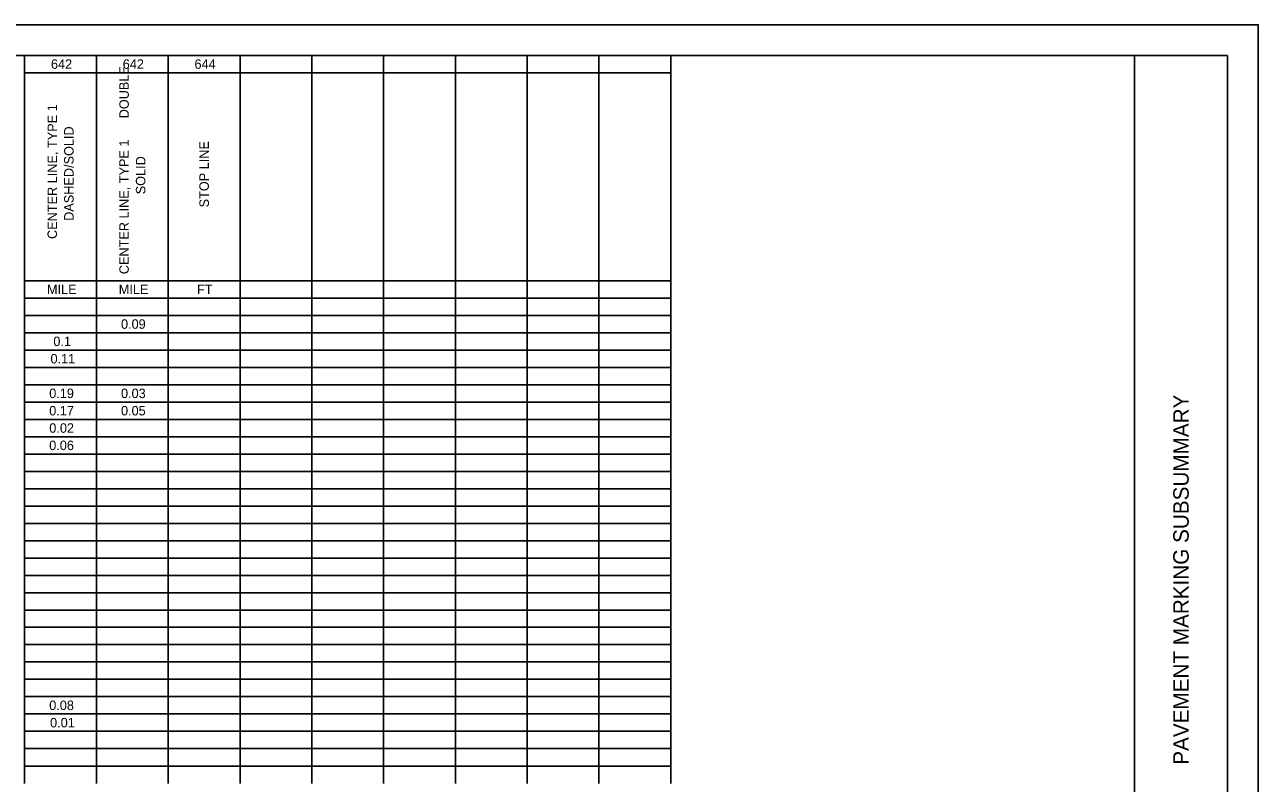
# Model space of a CAD drawing. Extents: x 0 to 34, y 0 to 22.
# Drawn here: x 14.06 to 34, y 9.74 to 22 of the extents above; entities that cross this region are included whole.
import ezdxf

# ---------------------------------------------------------------- set-up
doc = ezdxf.new("R2010")
doc.units = 0
for name, color, linetype in [('SH_Border', 7, 'Continuous'), ('SH_Cut_Line', 7, 'Continuous'), ('SH_Data', 7, 'Continuous'), ('SH_Text', 7, 'Continuous')]:
    doc.layers.add(name, color=color, linetype=linetype)

msp = doc.modelspace()

# ---------------------------------------------------------------- linework, layer by layer
at = {"layer": 'SH_Border'}
msp.add_line((32, 0.5), (32, 21.5), dxfattribs=at)
msp.add_lwpolyline([(1.5, 21.5), (33.5, 21.5), (33.5, 0.5), (1.5, 0.5)], close=True, dxfattribs=at)
at = {"layer": 'SH_Cut_Line'}
msp.add_lwpolyline([(0, 0), (34, 0), (34, 22), (0, 22)], close=True, dxfattribs=at)
at = {"layer": 'SH_Text'}
for p, q in [((14.062, 21.504), (16.383, 21.504)), ((14.062, 21.504), (14.062, 21.223)), ((15.222, 21.504), (15.222, 21.223)), ((16.383, 21.504), (21.024, 21.504)), ((16.383, 21.504), (16.383, 21.223)), ((17.543, 21.504), (17.543, 21.223)), ((18.703, 21.504), (18.703, 21.223)), ((19.863, 21.504), (19.863, 21.223)), ((21.024, 21.504), (23.344, 21.504)), ((21.024, 21.504), (21.024, 21.223)), ((22.184, 21.504), (22.184, 21.223)), ((23.344, 21.504), (24.504, 21.504)), ((23.344, 21.504), (23.344, 21.223)), ((24.504, 21.504), (24.504, 21.223)), ((14.062, 21.223), (16.383, 21.223)), ((14.062, 21.223), (14.062, 20.943)), ((15.222, 21.223), (15.222, 20.943)), ((16.383, 21.223), (21.024, 21.223)), ((16.383, 21.223), (16.383, 20.943)), ((17.543, 21.223), (17.543, 20.943)), ((18.703, 21.223), (18.703, 20.943)), ((19.863, 21.223), (19.863, 20.943)), ((21.024, 21.223), (23.344, 21.223)), ((21.024, 21.223), (21.024, 20.943)), ((22.184, 21.223), (22.184, 20.943)), ((23.344, 21.223), (24.504, 21.223)), ((23.344, 21.223), (23.344, 20.943)), ((24.504, 21.223), (24.504, 20.943)), ((14.062, 20.943), (14.062, 20.663)), ((15.222, 20.943), (15.222, 20.663)), ((16.383, 20.943), (16.383, 20.663)), ((17.543, 20.943), (17.543, 20.663)), ((18.703, 20.943), (18.703, 20.663)), ((19.863, 20.943), (19.863, 20.663)), ((21.024, 20.943), (21.024, 20.663)), ((22.184, 20.943), (22.184, 20.663)), ((23.344, 20.943), (23.344, 20.663)), ((24.504, 20.943), (24.504, 20.663)), ((14.062, 20.663), (14.062, 20.383)), ((15.222, 20.663), (15.222, 20.383)), ((16.383, 20.663), (16.383, 20.383)), ((17.543, 20.663), (17.543, 20.383)), ((18.703, 20.663), (18.703, 20.383)), ((19.863, 20.663), (19.863, 20.383)), ((21.024, 20.663), (21.024, 20.383)), ((22.184, 20.663), (22.184, 20.383)), ((23.344, 20.663), (23.344, 20.383)), ((24.504, 20.663), (24.504, 20.383)), ((14.062, 20.383), (14.062, 20.103)), ((15.222, 20.383), (15.222, 20.103)), ((16.383, 20.383), (16.383, 20.103)), ((17.543, 20.383), (17.543, 20.103)), ((18.703, 20.383), (18.703, 20.103)), ((19.863, 20.383), (19.863, 20.103)), ((21.024, 20.383), (21.024, 20.103)), ((22.184, 20.383), (22.184, 20.103)), ((23.344, 20.383), (23.344, 20.103)), ((24.504, 20.383), (24.504, 20.103)), ((14.062, 20.103), (14.062, 19.823)), ((15.222, 20.103), (15.222, 19.823)), ((16.383, 20.103), (16.383, 19.823)), ((17.543, 20.103), (17.543, 19.823)), ((18.703, 20.103), (18.703, 19.823)), ((19.863, 20.103), (19.863, 19.823)), ((21.024, 20.103), (21.024, 19.823)), ((22.184, 20.103), (22.184, 19.823)), ((23.344, 20.103), (23.344, 19.823)), ((24.504, 20.103), (24.504, 19.823)), ((14.062, 19.823), (14.062, 19.543)), ((15.222, 19.823), (15.222, 19.543)), ((16.383, 19.823), (16.383, 19.543)), ((17.543, 19.823), (17.543, 19.543)), ((18.703, 19.823), (18.703, 19.543)), ((19.863, 19.823), (19.863, 19.543)), ((21.024, 19.823), (21.024, 19.543)), ((22.184, 19.823), (22.184, 19.543)), ((23.344, 19.823), (23.344, 19.543)), ((24.504, 19.823), (24.504, 19.543)), ((14.062, 19.543), (14.062, 18.983)), ((15.222, 19.543), (15.222, 18.983)), ((16.383, 19.543), (16.383, 18.983)), ((17.543, 19.543), (17.543, 18.983)), ((18.703, 19.543), (18.703, 18.983)), ((19.863, 19.543), (19.863, 18.983)), ((21.024, 19.543), (21.024, 18.983)), ((22.184, 19.543), (22.184, 18.983)), ((23.344, 19.543), (23.344, 18.983)), ((24.504, 19.543), (24.504, 18.983)), ((14.062, 18.983), (14.062, 18.143)), ((15.222, 18.983), (15.222, 18.143)), ((16.383, 18.983), (16.383, 18.143)), ((17.543, 18.983), (17.543, 18.143)), ((18.703, 18.983), (18.703, 18.143)), ((19.863, 18.983), (19.863, 18.143)), ((21.024, 18.983), (21.024, 18.143)), ((22.184, 18.983), (22.184, 18.143)), ((23.344, 18.983), (23.344, 18.143)), ((24.504, 18.983), (24.504, 18.143)), ((14.062, 18.143), (14.062, 17.863)), ((15.222, 18.143), (15.222, 17.863)), ((16.383, 18.143), (16.383, 17.863)), ((17.543, 18.143), (17.543, 17.863)), ((18.703, 18.143), (18.703, 17.863)), ((19.863, 18.143), (19.863, 17.863)), ((21.024, 18.143), (21.024, 17.863)), ((22.184, 18.143), (22.184, 17.863)), ((23.344, 18.143), (23.344, 17.863)), ((24.504, 18.143), (24.504, 17.863)), ((14.062, 17.863), (16.383, 17.863)), ((14.062, 17.863), (14.062, 17.303)), ((15.222, 17.863), (15.222, 17.303)), ((16.383, 17.863), (21.024, 17.863)), ((16.383, 17.863), (16.383, 17.303)), ((17.543, 17.863), (17.543, 17.303)), ((18.703, 17.863), (18.703, 17.303)), ((19.863, 17.863), (19.863, 17.303)), ((21.024, 17.863), (23.344, 17.863)), ((21.024, 17.863), (21.024, 17.303)), ((22.184, 17.863), (22.184, 17.303)), ((23.344, 17.863), (24.504, 17.863)), ((23.344, 17.863), (23.344, 17.303)), ((24.504, 17.863), (24.504, 17.303)), ((14.062, 17.583), (16.383, 17.583)), ((16.383, 17.583), (21.024, 17.583)), ((21.024, 17.583), (23.344, 17.583)), ((23.344, 17.583), (24.504, 17.583)), ((14.062, 17.303), (16.383, 17.303)), ((14.062, 17.303), (14.062, 17.023)), ((15.222, 17.303), (15.222, 17.023)), ((16.383, 17.303), (21.024, 17.303)), ((16.383, 17.303), (16.383, 17.023)), ((17.543, 17.303), (17.543, 17.023)), ((18.703, 17.303), (18.703, 17.023)), ((19.863, 17.303), (19.863, 17.023)), ((21.024, 17.303), (23.344, 17.303)), ((21.024, 17.303), (21.024, 17.023)), ((22.184, 17.303), (22.184, 17.023)), ((23.344, 17.303), (24.504, 17.303)), ((23.344, 17.303), (23.344, 17.023)), ((24.504, 17.303), (24.504, 17.023)), ((14.062, 17.023), (16.383, 17.023)), ((14.062, 17.023), (14.062, 15.903)), ((15.222, 17.023), (15.222, 15.903)), ((16.383, 17.023), (21.024, 17.023)), ((16.383, 17.023), (16.383, 15.903)), ((17.543, 17.023), (17.543, 15.903)), ((18.703, 17.023), (18.703, 15.903)), ((19.863, 17.023), (19.863, 15.903)), ((21.024, 17.023), (23.344, 17.023)), ((21.024, 17.023), (21.024, 15.903)), ((22.184, 17.023), (22.184, 15.903)), ((23.344, 17.023), (24.504, 17.023)), ((23.344, 17.023), (23.344, 15.903)), ((24.504, 17.023), (24.504, 15.903)), ((14.062, 16.743), (16.383, 16.743)), ((16.383, 16.743), (21.024, 16.743)), ((21.024, 16.743), (23.344, 16.743)), ((23.344, 16.743), (24.504, 16.743)), ((14.062, 16.463), (16.383, 16.463)), ((16.383, 16.463), (21.024, 16.463)), ((21.024, 16.463), (23.344, 16.463)), ((23.344, 16.463), (24.504, 16.463)), ((14.062, 16.183), (16.383, 16.183)), ((16.383, 16.183), (21.024, 16.183)), ((21.024, 16.183), (23.344, 16.183)), ((23.344, 16.183), (24.504, 16.183)), ((14.062, 15.903), (16.383, 15.903)), ((14.062, 15.903), (14.062, 15.622)), ((15.222, 15.903), (15.222, 15.622)), ((16.383, 15.903), (21.024, 15.903)), ((16.383, 15.903), (16.383, 15.622)), ((17.543, 15.903), (17.543, 15.622)), ((18.703, 15.903), (18.703, 15.622)), ((19.863, 15.903), (19.863, 15.622)), ((21.024, 15.903), (23.344, 15.903)), ((21.024, 15.903), (21.024, 15.622)), ((22.184, 15.903), (22.184, 15.622)), ((23.344, 15.903), (24.504, 15.903)), ((23.344, 15.903), (23.344, 15.622)), ((24.504, 15.903), (24.504, 15.622)), ((14.062, 15.622), (16.383, 15.622)), ((14.062, 15.622), (14.062, 15.062)), ((15.222, 15.622), (15.222, 15.062)), ((16.383, 15.622), (21.024, 15.622)), ((16.383, 15.622), (16.383, 15.062)), ((17.543, 15.622), (17.543, 15.062)), ((18.703, 15.622), (18.703, 15.062)), ((19.863, 15.622), (19.863, 15.062)), ((21.024, 15.622), (23.344, 15.622)), ((21.024, 15.622), (21.024, 15.062)), ((22.184, 15.622), (22.184, 15.062)), ((23.344, 15.622), (24.504, 15.622)), ((23.344, 15.622), (23.344, 15.062)), ((24.504, 15.622), (24.504, 15.062)), ((14.062, 15.342), (16.383, 15.342)), ((16.383, 15.342), (21.024, 15.342)), ((21.024, 15.342), (23.344, 15.342)), ((23.344, 15.342), (24.504, 15.342)), ((14.062, 15.062), (16.383, 15.062)), ((14.062, 15.062), (14.062, 14.502)), ((15.222, 15.062), (15.222, 14.502)), ((16.383, 15.062), (21.024, 15.062)), ((16.383, 15.062), (16.383, 14.502)), ((17.543, 15.062), (17.543, 14.502)), ((18.703, 15.062), (18.703, 14.502)), ((19.863, 15.062), (19.863, 14.502)), ((21.024, 15.062), (23.344, 15.062)), ((21.024, 15.062), (21.024, 14.502)), ((22.184, 15.062), (22.184, 14.502)), ((23.344, 15.062), (24.504, 15.062)), ((23.344, 15.062), (23.344, 14.502)), ((24.504, 15.062), (24.504, 14.502)), ((14.062, 14.782), (16.383, 14.782)), ((16.383, 14.782), (21.024, 14.782)), ((21.024, 14.782), (23.344, 14.782)), ((23.344, 14.782), (24.504, 14.782)), ((14.062, 14.502), (16.383, 14.502)), ((14.062, 14.502), (14.062, 14.222)), ((15.222, 14.502), (15.222, 14.222)), ((16.383, 14.502), (21.024, 14.502)), ((16.383, 14.502), (16.383, 14.222)), ((17.543, 14.502), (17.543, 14.222)), ((18.703, 14.502), (18.703, 14.222)), ((19.863, 14.502), (19.863, 14.222)), ((21.024, 14.502), (23.344, 14.502)), ((21.024, 14.502), (21.024, 14.222)), ((22.184, 14.502), (22.184, 14.222)), ((23.344, 14.502), (24.504, 14.502)), ((23.344, 14.502), (23.344, 14.222)), ((24.504, 14.502), (24.504, 14.222)), ((14.062, 14.222), (16.383, 14.222)), ((14.062, 14.222), (14.062, 13.662)), ((15.222, 14.222), (15.222, 13.662)), ((16.383, 14.222), (21.024, 14.222)), ((16.383, 14.222), (16.383, 13.662)), ((17.543, 14.222), (17.543, 13.662)), ((18.703, 14.222), (18.703, 13.662)), ((19.863, 14.222), (19.863, 13.662)), ((21.024, 14.222), (23.344, 14.222)), ((21.024, 14.222), (21.024, 13.662)), ((22.184, 14.222), (22.184, 13.662)), ((23.344, 14.222), (24.504, 14.222)), ((23.344, 14.222), (23.344, 13.662)), ((24.504, 14.222), (24.504, 13.662)), ((14.062, 13.942), (16.383, 13.942)), ((16.383, 13.942), (21.024, 13.942)), ((21.024, 13.942), (23.344, 13.942)), ((23.344, 13.942), (24.504, 13.942)), ((14.062, 13.662), (16.383, 13.662)), ((14.062, 13.662), (14.062, 13.382)), ((15.222, 13.662), (15.222, 13.382)), ((16.383, 13.662), (21.024, 13.662)), ((16.383, 13.662), (16.383, 13.382)), ((17.543, 13.662), (17.543, 13.382)), ((18.703, 13.662), (18.703, 13.382)), ((19.863, 13.662), (19.863, 13.382)), ((21.024, 13.662), (23.344, 13.662)), ((21.024, 13.662), (21.024, 13.382)), ((22.184, 13.662), (22.184, 13.382)), ((23.344, 13.662), (24.504, 13.662)), ((23.344, 13.662), (23.344, 13.382)), ((24.504, 13.662), (24.504, 13.382)), ((14.062, 13.382), (16.383, 13.382)), ((14.062, 13.382), (14.062, 12.542)), ((15.222, 13.382), (15.222, 12.542)), ((16.383, 13.382), (21.024, 13.382)), ((16.383, 13.382), (16.383, 12.542)), ((17.543, 13.382), (17.543, 12.542)), ((18.703, 13.382), (18.703, 12.542)), ((19.863, 13.382), (19.863, 12.542)), ((21.024, 13.382), (23.344, 13.382)), ((21.024, 13.382), (21.024, 12.542)), ((22.184, 13.382), (22.184, 12.542)), ((23.344, 13.382), (24.504, 13.382)), ((23.344, 13.382), (23.344, 12.542)), ((24.504, 13.382), (24.504, 12.542)), ((14.062, 13.102), (16.383, 13.102)), ((16.383, 13.102), (21.024, 13.102)), ((21.024, 13.102), (23.344, 13.102)), ((23.344, 13.102), (24.504, 13.102)), ((14.062, 12.822), (16.383, 12.822)), ((16.383, 12.822), (21.024, 12.822)), ((21.024, 12.822), (23.344, 12.822)), ((23.344, 12.822), (24.504, 12.822)), ((14.062, 12.542), (16.383, 12.542)), ((14.062, 12.542), (14.062, 11.982)), ((15.222, 12.542), (15.222, 11.982)), ((16.383, 12.542), (21.024, 12.542)), ((16.383, 12.542), (16.383, 11.982)), ((17.543, 12.542), (17.543, 11.982)), ((18.703, 12.542), (18.703, 11.982)), ((19.863, 12.542), (19.863, 11.982)), ((21.024, 12.542), (23.344, 12.542)), ((21.024, 12.542), (21.024, 11.982)), ((22.184, 12.542), (22.184, 11.982)), ((23.344, 12.542), (24.504, 12.542)), ((23.344, 12.542), (23.344, 11.982)), ((24.504, 12.542), (24.504, 11.982)), ((14.062, 12.262), (16.383, 12.262)), ((16.383, 12.262), (21.024, 12.262)), ((21.024, 12.262), (23.344, 12.262)), ((23.344, 12.262), (24.504, 12.262)), ((14.062, 11.982), (16.383, 11.982)), ((14.062, 11.982), (14.062, 11.142)), ((15.222, 11.982), (15.222, 11.142)), ((16.383, 11.982), (21.024, 11.982)), ((16.383, 11.982), (16.383, 11.142)), ((17.543, 11.982), (17.543, 11.142)), ((18.703, 11.982), (18.703, 11.142)), ((19.863, 11.982), (19.863, 11.142)), ((21.024, 11.982), (23.344, 11.982)), ((21.024, 11.982), (21.024, 11.142)), ((22.184, 11.982), (22.184, 11.142)), ((23.344, 11.982), (24.504, 11.982)), ((23.344, 11.982), (23.344, 11.142)), ((24.504, 11.982), (24.504, 11.142)), ((14.062, 11.702), (16.383, 11.702)), ((16.383, 11.702), (21.024, 11.702)), ((21.024, 11.702), (23.344, 11.702)), ((23.344, 11.702), (24.504, 11.702)), ((14.062, 11.422), (16.383, 11.422)), ((16.383, 11.422), (21.024, 11.422)), ((21.024, 11.422), (23.344, 11.422)), ((23.344, 11.422), (24.504, 11.422)), ((14.062, 11.142), (16.383, 11.142)), ((14.062, 11.142), (14.062, 10.582)), ((15.222, 11.142), (15.222, 10.582)), ((16.383, 11.142), (21.024, 11.142)), ((16.383, 11.142), (16.383, 10.582)), ((17.543, 11.142), (17.543, 10.582)), ((18.703, 11.142), (18.703, 10.582)), ((19.863, 11.142), (19.863, 10.582)), ((21.024, 11.142), (23.344, 11.142)), ((21.024, 11.142), (21.024, 10.582)), ((22.184, 11.142), (22.184, 10.582)), ((23.344, 11.142), (24.504, 11.142)), ((23.344, 11.142), (23.344, 10.582)), ((24.504, 11.142), (24.504, 10.582)), ((14.062, 10.862), (16.383, 10.862)), ((16.383, 10.862), (21.024, 10.862)), ((21.024, 10.862), (23.344, 10.862)), ((23.344, 10.862), (24.504, 10.862)), ((14.062, 10.582), (16.383, 10.582)), ((14.062, 10.582), (14.062, 9.741)), ((15.222, 10.582), (15.222, 9.741)), ((16.383, 10.582), (21.024, 10.582)), ((16.383, 10.582), (16.383, 9.741)), ((17.543, 10.582), (17.543, 9.741)), ((18.703, 10.582), (18.703, 9.741)), ((19.863, 10.582), (19.863, 9.741)), ((21.024, 10.582), (23.344, 10.582)), ((21.024, 10.582), (21.024, 9.741)), ((22.184, 10.582), (22.184, 9.741)), ((23.344, 10.582), (24.504, 10.582)), ((23.344, 10.582), (23.344, 9.741)), ((24.504, 10.582), (24.504, 9.741)), ((14.062, 10.302), (16.383, 10.302)), ((16.383, 10.302), (21.024, 10.302)), ((21.024, 10.302), (23.344, 10.302)), ((23.344, 10.302), (24.504, 10.302)), ((14.062, 10.021), (16.383, 10.021)), ((16.383, 10.021), (21.024, 10.021)), ((21.024, 10.021), (23.344, 10.021)), ((23.344, 10.021), (24.504, 10.021))]:
    msp.add_line(p, q, dxfattribs=at)

# ---------------------------------------------------------------- texts
at = {"layer": 'SH_Data'}
msp.add_text('PAVEMENT MARKING SUBSUMMARY', height=0.25, rotation=90, dxfattribs=at).set_placement((32.875, 10.041))
at = {"layer": 'SH_Text'}
for s, p in [('642', (14.487, 21.287)), ('642', (15.647, 21.287)), ('644', (16.807, 21.287)), ('MILE', (14.423, 17.646)), ('MILE', (15.583, 17.646)), ('FT', (16.847, 17.646)), ('0.09', (15.619, 17.086)), ('0.1', (14.526, 16.806)), ('0.11', (14.48, 16.526)), ('0.19', (14.459, 15.966)), ('0.03', (15.619, 15.966)), ('0.17', (14.459, 15.686)), ('0.05', (15.619, 15.686)), ('0.02', (14.46, 15.406)), ('0.06', (14.459, 15.126)), ('0.08', (14.459, 10.925)), ('0.01', (14.473, 10.645))]:
    msp.add_text(s, height=0.1534, dxfattribs=at).set_placement(p)
for s, height, p in [('CENTER LINE, TYPE 1      DOUBLE ', 0.15336, (15.745, 17.968)), ('CENTER LINE, TYPE 1 ', 0.15336, (14.585, 18.537)), ('DASHED/SOLID', 0.15336, (14.853, 18.83)), ('STOP LINE', 0.1534, (17.039, 19.048)), ('SOLID', 0.1534, (16.013, 19.259))]:
    msp.add_text(s, height=height, rotation=90, dxfattribs=at).set_placement(p)

doc.saveas('drawing.dxf')
